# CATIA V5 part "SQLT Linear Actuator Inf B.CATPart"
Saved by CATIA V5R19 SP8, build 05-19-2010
Part number: SQLT Linear Actuator Inf B
Publications: "Droite.1", "Plan.1", "Droite.2", "Plan.2", "Droite.3"
Bounding box of the stored display mesh (mm): x -150 to 150, y 10 to 410, z 570 to 670
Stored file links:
  G:\EU_thinkMotion\CFAO_2010\MMS_groupe3\MMS_groupe3\A reprendre\fovide\fovide\SQLT Linear Actuator Inf B.CATPart
  G:\EU_thinkMotion\CFAO_2010\MMS_groupe3\MMS_groupe3\A reprendre\fovide\fovide\fovide.CATProduct
  G:\EU_thinkMotion\CFAO_2010\MMS_groupe3\MMS_groupe3\A reprendre\fovide\fovide\Linear Actuator Inf A.CATPart
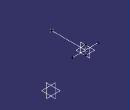
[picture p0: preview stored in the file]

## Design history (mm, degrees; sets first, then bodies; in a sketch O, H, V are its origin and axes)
Set1
  Point1 "Point.N": linked copy from another document
  Point2 "Point.O": linked copy from another document
Set2 "set SQLT Linear Actuator Inf B"
  Line1: type PtPt, FirstPoint Point1, SecondPoint Point2
  Plane1: type OffsetPt, RefPlane yz-plane, RefPoint Point1
  Line2: type Normal, RefPoint Point1, RefSkin Plane1, Start -150, End 150
  Plane2: type OffsetPt, RefPlane xy-plane, RefPoint Point1
  Line3: type Normal, RefPoint Point1, RefSkin Plane2, Start -50, End 50
Body1 (main body)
